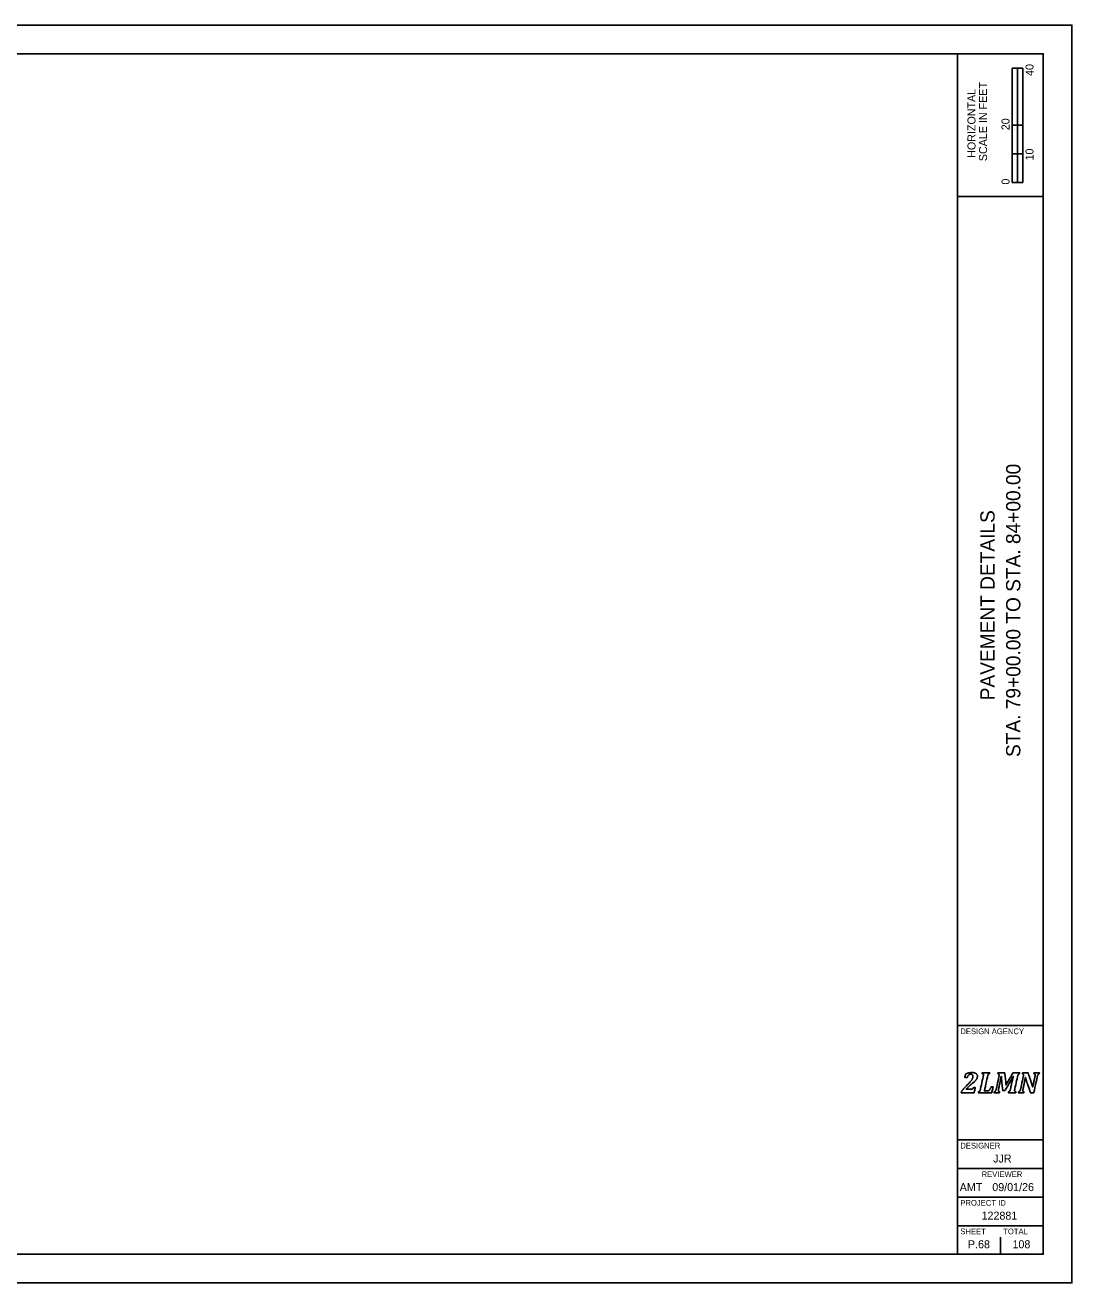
# Model space of a CAD drawing. Extents: x -2.6 to 34, y 0 to 22.
# Drawn here: x 15.7 to 34, y 0 to 22 of the extents above; entities that cross this region are included whole.
import ezdxf

# ---------------------------------------------------------------- set-up
doc = ezdxf.new("R2010")
doc.units = 0
for name, color, linetype in [('SH_Border', 7, 'Continuous'), ('SH_Cut_Line', 7, 'Continuous'), ('SH_Data', 7, 'Continuous')]:
    doc.layers.add(name, color=color, linetype=linetype)

msp = doc.modelspace()

# ---------------------------------------------------------------- linework, layer by layer
at = {"layer": 'SH_Border'}
for p, q in [((32, 0.5), (32, 21.5)), ((32, 19), (33.5, 19)), ((32, 4.5), (33.5, 4.5)), ((32, 2.5), (33.5, 2.5)), ((32, 2), (33.5, 2)), ((32, 1.5), (33.5, 1.5)), ((32, 1), (33.5, 1))]:
    msp.add_line(p, q, dxfattribs=at)
msp.add_lwpolyline([(1.5, 21.5), (33.5, 21.5), (33.5, 0.5), (1.5, 0.5)], close=True, dxfattribs=at)
at = {"layer": 'SH_Cut_Line'}
msp.add_lwpolyline([(0, 0), (34, 0), (34, 22), (0, 22)], close=True, dxfattribs=at)
at = {"layer": 'SH_Data'}
for p, q in [((32.957, 19.25), (32.957, 21.25)), ((33.144, 21.25), (32.957, 21.25)), ((32.957, 20.25), (32.957, 21.25)), ((32.957, 21.25), (33.05, 21.25)), ((33.05, 21.25), (33.051, 21.25)), ((33.051, 21.25), (33.051, 20.25)), ((33.144, 21.25), (33.144, 19.25)), ((33.051, 20.25), (32.957, 20.25)), ((33.143, 20.25), (33.05, 20.25)), ((33.05, 20.25), (33.05, 19.75)), ((33.143, 19.75), (33.143, 20.25)), ((33.05, 19.75), (32.957, 19.75)), ((32.957, 19.75), (32.957, 19.25)), ((33.05, 19.25), (33.05, 19.75)), ((33.05, 19.75), (33.143, 19.75)), ((33.144, 19.25), (32.957, 19.25)), ((32.957, 19.25), (33.05, 19.25)), ((32.75, 3.5), (32.75, 3.5)), ((32.375, 0.675), (32.375, 0.675)), ((32.75, 0.5), (32.75, 0.8))]:
    msp.add_line(p, q, dxfattribs=at)
for points in [[(32.237, 3.388), (32.246, 3.388), (32.253, 3.389), (32.258, 3.39), (32.263, 3.392), (32.267, 3.394), (32.27, 3.397), (32.273, 3.401), (32.277, 3.408), (32.281, 3.417), (32.281, 3.417), (32.312, 3.417), (32.312, 3.417), (32.312, 3.417), (32.29, 3.326), (32.29, 3.326), (32.29, 3.326), (32.066, 3.326), (32.066, 3.326), (32.066, 3.326), (32.069, 3.343), (32.069, 3.343), (32.078, 3.358), (32.091, 3.375), (32.106, 3.394), (32.122, 3.412), (32.144, 3.435), (32.172, 3.462), (32.197, 3.486), (32.217, 3.506), (32.23, 3.521), (32.243, 3.537), (32.253, 3.551), (32.259, 3.566), (32.266, 3.58), (32.269, 3.595), (32.269, 3.61), (32.269, 3.622), (32.266, 3.632), (32.26, 3.64), (32.253, 3.647), (32.245, 3.65), (32.234, 3.65), (32.22, 3.65), (32.208, 3.646), (32.198, 3.636), (32.188, 3.627), (32.18, 3.613), (32.172, 3.593), (32.172, 3.593), (32.126, 3.593), (32.126, 3.593), (32.126, 3.593), (32.14, 3.654), (32.14, 3.654), (32.166, 3.663), (32.188, 3.669), (32.205, 3.673), (32.223, 3.676), (32.24, 3.678), (32.258, 3.678), (32.278, 3.678), (32.295, 3.675), (32.309, 3.669), (32.322, 3.664), (32.332, 3.656), (32.339, 3.646), (32.345, 3.637), (32.348, 3.626), (32.348, 3.613), (32.348, 3.602), (32.346, 3.591), (32.342, 3.581), (32.339, 3.571), (32.333, 3.56), (32.324, 3.549), (32.315, 3.539), (32.304, 3.526), (32.289, 3.513), (32.275, 3.499), (32.254, 3.482), (32.228, 3.46), (32.216, 3.45), (32.202, 3.438), (32.188, 3.425), (32.174, 3.412), (32.162, 3.4), (32.154, 3.391), (32.154, 3.391), (32.153, 3.388), (32.153, 3.388), (32.153, 3.388), (32.237, 3.388), (32.237, 3.388)], [(32.237, 3.388), (32.237, 3.388), (32.153, 3.388), (32.153, 3.388), (32.153, 3.388), (32.154, 3.391), (32.154, 3.391), (32.162, 3.4), (32.174, 3.412), (32.188, 3.425), (32.202, 3.438), (32.216, 3.45), (32.228, 3.46), (32.254, 3.482), (32.275, 3.499), (32.289, 3.513), (32.304, 3.526), (32.315, 3.539), (32.324, 3.549), (32.333, 3.56), (32.339, 3.571), (32.342, 3.581), (32.346, 3.591), (32.348, 3.602), (32.348, 3.613), (32.348, 3.626), (32.345, 3.637), (32.339, 3.646), (32.332, 3.656), (32.322, 3.664), (32.309, 3.669), (32.295, 3.675), (32.278, 3.678), (32.258, 3.678), (32.24, 3.678), (32.223, 3.676), (32.205, 3.673), (32.188, 3.669), (32.166, 3.663), (32.14, 3.654), (32.14, 3.654), (32.126, 3.593), (32.126, 3.593), (32.126, 3.593), (32.172, 3.593), (32.172, 3.593), (32.18, 3.613), (32.188, 3.627), (32.198, 3.636), (32.208, 3.646), (32.22, 3.65), (32.234, 3.65), (32.245, 3.65), (32.253, 3.647), (32.26, 3.64), (32.266, 3.632), (32.269, 3.622), (32.269, 3.61), (32.269, 3.595), (32.266, 3.58), (32.259, 3.566), (32.253, 3.551), (32.243, 3.537), (32.23, 3.521), (32.217, 3.506), (32.197, 3.486), (32.172, 3.462), (32.144, 3.435), (32.122, 3.412), (32.106, 3.394), (32.091, 3.375), (32.078, 3.358), (32.069, 3.343), (32.069, 3.343), (32.066, 3.326), (32.066, 3.326), (32.066, 3.326), (32.29, 3.326), (32.29, 3.326), (32.29, 3.326), (32.312, 3.417), (32.312, 3.417), (32.312, 3.417), (32.281, 3.417), (32.281, 3.417), (32.277, 3.408), (32.273, 3.401), (32.27, 3.397), (32.267, 3.394), (32.263, 3.392), (32.258, 3.39), (32.253, 3.389), (32.246, 3.388), (32.237, 3.388)], [(32.518, 3.356), (32.527, 3.356), (32.533, 3.357), (32.538, 3.358), (32.542, 3.36), (32.546, 3.362), (32.55, 3.365), (32.554, 3.368), (32.558, 3.372), (32.562, 3.377), (32.567, 3.382), (32.571, 3.388), (32.576, 3.397), (32.58, 3.405), (32.585, 3.415), (32.589, 3.427), (32.589, 3.427), (32.624, 3.427), (32.624, 3.427), (32.624, 3.427), (32.598, 3.326), (32.598, 3.326), (32.598, 3.326), (32.365, 3.326), (32.365, 3.326), (32.365, 3.326), (32.369, 3.343), (32.369, 3.343), (32.376, 3.345), (32.381, 3.348), (32.385, 3.351), (32.389, 3.355), (32.392, 3.36), (32.395, 3.366), (32.398, 3.373), (32.4, 3.382), (32.403, 3.395), (32.403, 3.395), (32.449, 3.605), (32.449, 3.605), (32.452, 3.615), (32.453, 3.625), (32.453, 3.635), (32.453, 3.642), (32.451, 3.647), (32.448, 3.651), (32.444, 3.654), (32.439, 3.656), (32.432, 3.657), (32.432, 3.657), (32.435, 3.674), (32.435, 3.674), (32.435, 3.674), (32.563, 3.674), (32.563, 3.674), (32.563, 3.674), (32.559, 3.657), (32.559, 3.657), (32.552, 3.655), (32.547, 3.652), (32.543, 3.649), (32.539, 3.645), (32.536, 3.64), (32.533, 3.634), (32.531, 3.627), (32.528, 3.618), (32.525, 3.605), (32.525, 3.605), (32.47, 3.356), (32.47, 3.356), (32.47, 3.356), (32.518, 3.356), (32.518, 3.356)], [(32.518, 3.356), (32.518, 3.356), (32.47, 3.356), (32.47, 3.356), (32.47, 3.356), (32.525, 3.605), (32.525, 3.605), (32.528, 3.618), (32.531, 3.627), (32.533, 3.634), (32.536, 3.64), (32.539, 3.645), (32.543, 3.649), (32.547, 3.652), (32.552, 3.655), (32.559, 3.657), (32.559, 3.657), (32.563, 3.674), (32.563, 3.674), (32.563, 3.674), (32.435, 3.674), (32.435, 3.674), (32.435, 3.674), (32.432, 3.657), (32.432, 3.657), (32.439, 3.656), (32.444, 3.654), (32.448, 3.651), (32.451, 3.647), (32.453, 3.642), (32.453, 3.635), (32.453, 3.625), (32.452, 3.615), (32.449, 3.605), (32.449, 3.605), (32.403, 3.395), (32.403, 3.395), (32.4, 3.382), (32.398, 3.373), (32.395, 3.366), (32.392, 3.36), (32.389, 3.355), (32.385, 3.351), (32.381, 3.348), (32.376, 3.345), (32.369, 3.343), (32.369, 3.343), (32.365, 3.326), (32.365, 3.326), (32.365, 3.326), (32.598, 3.326), (32.598, 3.326), (32.598, 3.326), (32.624, 3.427), (32.624, 3.427), (32.624, 3.427), (32.589, 3.427), (32.589, 3.427), (32.585, 3.415), (32.58, 3.405), (32.576, 3.397), (32.571, 3.388), (32.567, 3.382), (32.562, 3.377), (32.558, 3.372), (32.554, 3.368), (32.55, 3.365), (32.546, 3.362), (32.542, 3.36), (32.538, 3.358), (32.533, 3.357), (32.527, 3.356), (32.518, 3.356)], [(32.829, 3.674), (32.829, 3.674), (32.849, 3.461), (32.849, 3.461), (32.849, 3.461), (32.969, 3.674), (32.969, 3.674), (32.969, 3.674), (33.087, 3.674), (33.087, 3.674), (33.087, 3.674), (33.084, 3.657), (33.084, 3.657), (33.077, 3.655), (33.071, 3.652), (33.067, 3.649), (33.064, 3.645), (33.06, 3.64), (33.058, 3.634), (33.055, 3.627), (33.052, 3.618), (33.05, 3.605), (33.05, 3.605), (33.003, 3.395), (33.003, 3.395), (33.002, 3.39), (33.002, 3.387), (33.001, 3.384), (33.001, 3.382), (33.001, 3.379), (33, 3.376), (33, 3.373), (33, 3.369), (33, 3.365), (33, 3.358), (33.002, 3.353), (33.005, 3.349), (33.008, 3.346), (33.014, 3.344), (33.021, 3.343), (33.021, 3.343), (33.018, 3.326), (33.018, 3.326), (33.018, 3.326), (32.89, 3.326), (32.89, 3.326), (32.89, 3.326), (32.893, 3.343), (32.893, 3.343), (32.9, 3.345), (32.906, 3.348), (32.91, 3.351), (32.914, 3.355), (32.917, 3.36), (32.919, 3.366), (32.922, 3.373), (32.925, 3.382), (32.928, 3.395), (32.928, 3.395), (32.951, 3.502), (32.951, 3.502), (32.954, 3.513), (32.957, 3.529), (32.962, 3.548), (32.967, 3.568), (32.972, 3.588), (32.978, 3.609), (32.978, 3.609), (32.973, 3.609), (32.973, 3.609), (32.965, 3.594), (32.957, 3.579), (32.948, 3.563), (32.948, 3.563), (32.833, 3.364), (32.833, 3.364), (32.833, 3.364), (32.792, 3.364), (32.792, 3.364), (32.792, 3.364), (32.775, 3.518), (32.775, 3.518), (32.773, 3.537), (32.772, 3.554), (32.77, 3.569), (32.769, 3.583), (32.768, 3.597), (32.768, 3.611), (32.768, 3.611), (32.764, 3.611), (32.764, 3.611), (32.761, 3.596), (32.758, 3.578), (32.755, 3.558), (32.751, 3.538), (32.747, 3.521), (32.744, 3.507), (32.744, 3.507), (32.72, 3.395), (32.72, 3.395), (32.719, 3.39), (32.718, 3.387), (32.718, 3.384), (32.717, 3.382), (32.717, 3.379), (32.717, 3.376), (32.717, 3.373), (32.716, 3.369), (32.716, 3.365), (32.716, 3.358), (32.718, 3.353), (32.721, 3.349), (32.725, 3.346), (32.73, 3.344), (32.738, 3.343), (32.738, 3.343), (32.734, 3.326), (32.734, 3.326), (32.734, 3.326), (32.641, 3.326), (32.641, 3.326), (32.641, 3.326), (32.644, 3.343), (32.644, 3.343), (32.651, 3.345), (32.657, 3.348), (32.661, 3.351), (32.665, 3.355), (32.668, 3.36), (32.67, 3.366), (32.673, 3.373), (32.676, 3.382), (32.679, 3.395), (32.679, 3.395), (32.725, 3.605), (32.725, 3.605), (32.727, 3.615), (32.728, 3.625), (32.728, 3.635), (32.728, 3.642), (32.727, 3.647), (32.723, 3.651), (32.72, 3.654), (32.715, 3.656), (32.707, 3.657), (32.707, 3.657), (32.711, 3.674), (32.711, 3.674), (32.711, 3.674), (32.829, 3.674), (32.829, 3.674)], [(32.829, 3.674), (32.829, 3.674), (32.711, 3.674), (32.711, 3.674), (32.711, 3.674), (32.707, 3.657), (32.707, 3.657), (32.715, 3.656), (32.72, 3.654), (32.723, 3.651), (32.727, 3.647), (32.728, 3.642), (32.728, 3.635), (32.728, 3.625), (32.727, 3.615), (32.725, 3.605), (32.725, 3.605), (32.679, 3.395), (32.679, 3.395), (32.676, 3.382), (32.673, 3.373), (32.67, 3.366), (32.668, 3.36), (32.665, 3.355), (32.661, 3.351), (32.657, 3.348), (32.651, 3.345), (32.644, 3.343), (32.644, 3.343), (32.641, 3.326), (32.641, 3.326), (32.641, 3.326), (32.734, 3.326), (32.734, 3.326), (32.734, 3.326), (32.738, 3.343), (32.738, 3.343), (32.73, 3.344), (32.725, 3.346), (32.721, 3.349), (32.718, 3.353), (32.716, 3.358), (32.716, 3.365), (32.716, 3.369), (32.717, 3.373), (32.717, 3.376), (32.717, 3.379), (32.717, 3.382), (32.718, 3.384), (32.718, 3.387), (32.719, 3.39), (32.72, 3.395), (32.72, 3.395), (32.744, 3.507), (32.744, 3.507), (32.747, 3.521), (32.751, 3.538), (32.755, 3.558), (32.758, 3.578), (32.761, 3.596), (32.764, 3.611), (32.764, 3.611), (32.768, 3.611), (32.768, 3.611), (32.768, 3.597), (32.769, 3.583), (32.77, 3.569), (32.772, 3.554), (32.773, 3.537), (32.775, 3.518), (32.775, 3.518), (32.792, 3.364), (32.792, 3.364), (32.792, 3.364), (32.833, 3.364), (32.833, 3.364), (32.833, 3.364), (32.948, 3.563), (32.948, 3.563), (32.957, 3.579), (32.965, 3.594), (32.973, 3.609), (32.973, 3.609), (32.978, 3.609), (32.978, 3.609), (32.972, 3.588), (32.967, 3.568), (32.962, 3.548), (32.957, 3.529), (32.954, 3.513), (32.951, 3.502), (32.951, 3.502), (32.928, 3.395), (32.928, 3.395), (32.925, 3.382), (32.922, 3.373), (32.919, 3.366), (32.917, 3.36), (32.914, 3.355), (32.91, 3.351), (32.906, 3.348), (32.9, 3.345), (32.893, 3.343), (32.893, 3.343), (32.89, 3.326), (32.89, 3.326), (32.89, 3.326), (33.018, 3.326), (33.018, 3.326), (33.018, 3.326), (33.021, 3.343), (33.021, 3.343), (33.014, 3.344), (33.008, 3.346), (33.005, 3.349), (33.002, 3.353), (33, 3.358), (33, 3.365), (33, 3.369), (33, 3.373), (33, 3.376), (33.001, 3.379), (33.001, 3.382), (33.001, 3.384), (33.002, 3.387), (33.002, 3.39), (33.003, 3.395), (33.003, 3.395), (33.05, 3.605), (33.05, 3.605), (33.052, 3.618), (33.055, 3.627), (33.058, 3.634), (33.06, 3.64), (33.064, 3.645), (33.067, 3.649), (33.071, 3.652), (33.077, 3.655), (33.084, 3.657), (33.084, 3.657), (33.087, 3.674), (33.087, 3.674), (33.087, 3.674), (32.969, 3.674), (32.969, 3.674), (32.969, 3.674), (32.849, 3.461), (32.849, 3.461), (32.849, 3.461), (32.829, 3.674), (32.829, 3.674)], [(33.137, 3.674), (33.137, 3.674), (33.234, 3.674), (33.234, 3.674), (33.234, 3.674), (33.283, 3.53), (33.283, 3.53), (33.296, 3.49), (33.307, 3.456), (33.315, 3.426), (33.315, 3.426), (33.318, 3.426), (33.318, 3.426), (33.323, 3.455), (33.329, 3.488), (33.337, 3.523), (33.337, 3.523), (33.355, 3.605), (33.355, 3.605), (33.357, 3.615), (33.358, 3.625), (33.358, 3.635), (33.358, 3.642), (33.357, 3.647), (33.353, 3.651), (33.35, 3.654), (33.345, 3.656), (33.337, 3.657), (33.337, 3.657), (33.341, 3.674), (33.341, 3.674), (33.341, 3.674), (33.434, 3.674), (33.434, 3.674), (33.434, 3.674), (33.431, 3.657), (33.431, 3.657), (33.424, 3.655), (33.418, 3.652), (33.414, 3.649), (33.41, 3.645), (33.407, 3.64), (33.405, 3.634), (33.402, 3.627), (33.399, 3.618), (33.396, 3.605), (33.396, 3.605), (33.335, 3.326), (33.335, 3.326), (33.335, 3.326), (33.277, 3.326), (33.277, 3.326), (33.277, 3.326), (33.216, 3.504), (33.216, 3.504), (33.211, 3.518), (33.207, 3.531), (33.204, 3.543), (33.2, 3.556), (33.195, 3.571), (33.19, 3.59), (33.19, 3.59), (33.186, 3.59), (33.186, 3.59), (33.185, 3.579), (33.182, 3.563), (33.179, 3.543), (33.175, 3.523), (33.17, 3.501), (33.165, 3.478), (33.165, 3.478), (33.147, 3.395), (33.147, 3.395), (33.146, 3.39), (33.145, 3.387), (33.145, 3.384), (33.144, 3.382), (33.144, 3.379), (33.144, 3.376), (33.143, 3.373), (33.143, 3.369), (33.143, 3.365), (33.143, 3.358), (33.145, 3.353), (33.148, 3.349), (33.152, 3.346), (33.157, 3.344), (33.164, 3.343), (33.164, 3.343), (33.161, 3.326), (33.161, 3.326), (33.161, 3.326), (33.067, 3.326), (33.067, 3.326), (33.067, 3.326), (33.071, 3.343), (33.071, 3.343), (33.078, 3.345), (33.083, 3.348), (33.087, 3.351), (33.091, 3.355), (33.094, 3.36), (33.097, 3.366), (33.1, 3.373), (33.102, 3.382), (33.105, 3.395), (33.105, 3.395), (33.151, 3.605), (33.151, 3.605), (33.154, 3.615), (33.155, 3.625), (33.155, 3.635), (33.155, 3.642), (33.153, 3.647), (33.15, 3.651), (33.146, 3.654), (33.141, 3.656), (33.134, 3.657), (33.134, 3.657), (33.137, 3.674), (33.137, 3.674)], [(33.137, 3.674), (33.137, 3.674), (33.134, 3.657), (33.134, 3.657), (33.141, 3.656), (33.146, 3.654), (33.15, 3.651), (33.153, 3.647), (33.155, 3.642), (33.155, 3.635), (33.155, 3.625), (33.154, 3.615), (33.151, 3.605), (33.151, 3.605), (33.105, 3.395), (33.105, 3.395), (33.102, 3.382), (33.1, 3.373), (33.097, 3.366), (33.094, 3.36), (33.091, 3.355), (33.087, 3.351), (33.083, 3.348), (33.078, 3.345), (33.071, 3.343), (33.071, 3.343), (33.067, 3.326), (33.067, 3.326), (33.067, 3.326), (33.161, 3.326), (33.161, 3.326), (33.161, 3.326), (33.164, 3.343), (33.164, 3.343), (33.157, 3.344), (33.152, 3.346), (33.148, 3.349), (33.145, 3.353), (33.143, 3.358), (33.143, 3.365), (33.143, 3.369), (33.143, 3.373), (33.144, 3.376), (33.144, 3.379), (33.144, 3.382), (33.145, 3.384), (33.145, 3.387), (33.146, 3.39), (33.147, 3.395), (33.147, 3.395), (33.165, 3.478), (33.165, 3.478), (33.17, 3.501), (33.175, 3.523), (33.179, 3.543), (33.182, 3.563), (33.185, 3.579), (33.186, 3.59), (33.186, 3.59), (33.19, 3.59), (33.19, 3.59), (33.195, 3.571), (33.2, 3.556), (33.204, 3.543), (33.207, 3.531), (33.211, 3.518), (33.216, 3.504), (33.216, 3.504), (33.277, 3.326), (33.277, 3.326), (33.277, 3.326), (33.335, 3.326), (33.335, 3.326), (33.335, 3.326), (33.396, 3.605), (33.396, 3.605), (33.399, 3.618), (33.402, 3.627), (33.405, 3.634), (33.407, 3.64), (33.41, 3.645), (33.414, 3.649), (33.418, 3.652), (33.424, 3.655), (33.431, 3.657), (33.431, 3.657), (33.434, 3.674), (33.434, 3.674), (33.434, 3.674), (33.341, 3.674), (33.341, 3.674), (33.341, 3.674), (33.337, 3.657), (33.337, 3.657), (33.345, 3.656), (33.35, 3.654), (33.353, 3.651), (33.357, 3.647), (33.358, 3.642), (33.358, 3.635), (33.358, 3.625), (33.357, 3.615), (33.355, 3.605), (33.355, 3.605), (33.337, 3.523), (33.337, 3.523), (33.329, 3.488), (33.323, 3.455), (33.318, 3.426), (33.318, 3.426), (33.315, 3.426), (33.315, 3.426), (33.307, 3.456), (33.296, 3.49), (33.283, 3.53), (33.283, 3.53), (33.234, 3.674), (33.234, 3.674), (33.234, 3.674), (33.137, 3.674), (33.137, 3.674)]]:
    msp.add_open_spline(points, degree=3, dxfattribs=at)

# ---------------------------------------------------------------- texts
for s, height, p in [('40', 0.14, (33.33, 21.112)), ('SCALE IN FEET', 0.14, (32.517, 19.621)), ('HORIZONTAL', 0.14, (32.315, 19.679)), ('20', 0.14, (32.91, 20.162)), ('10', 0.14, (33.33, 19.633)), ('0', 0.14, (32.91, 19.211)), ('STA. 79+00.00 TO STA. 84+00.00', 0.25, (33.1, 9.198)), ('PAVEMENT DETAILS', 0.25, (32.65, 10.19))]:
    msp.add_text(s, height=height, rotation=90, dxfattribs=at).set_placement(p)
for s, height, p in [('DESIGN AGENCY', 0.1, (32.05, 4.35)), ('DESIGNER', 0.1, (32.05, 2.35)), ('JJR', 0.14, (32.624, 2.105)), ('REVIEWER', 0.1, (32.422, 1.85)), ('AMT', 0.14, (32.039, 1.605)), ('09/01/26', 0.14, (32.609, 1.605)), ('PROJECT ID', 0.1, (32.05, 1.35)), ('122881', 0.14, (32.421, 1.105)), ('SHEET', 0.1, (32.05, 0.85)), ('TOTAL', 0.1, (32.8, 0.85)), ('P.68', 0.14, (32.183, 0.605)), ('108', 0.14, (32.962, 0.605))]:
    msp.add_text(s, height=height, dxfattribs=at).set_placement(p)

doc.saveas('drawing.dxf')
